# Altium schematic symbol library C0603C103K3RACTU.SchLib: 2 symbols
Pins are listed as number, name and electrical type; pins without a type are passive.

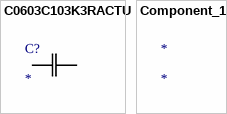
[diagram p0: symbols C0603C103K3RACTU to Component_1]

## C0603C103K3RACTU
designator C?
No Description Available; Mfr_Name: Kemet
footprint CAPC17595_87N_KEM
pins: 1, 2

## Component_1
designator *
